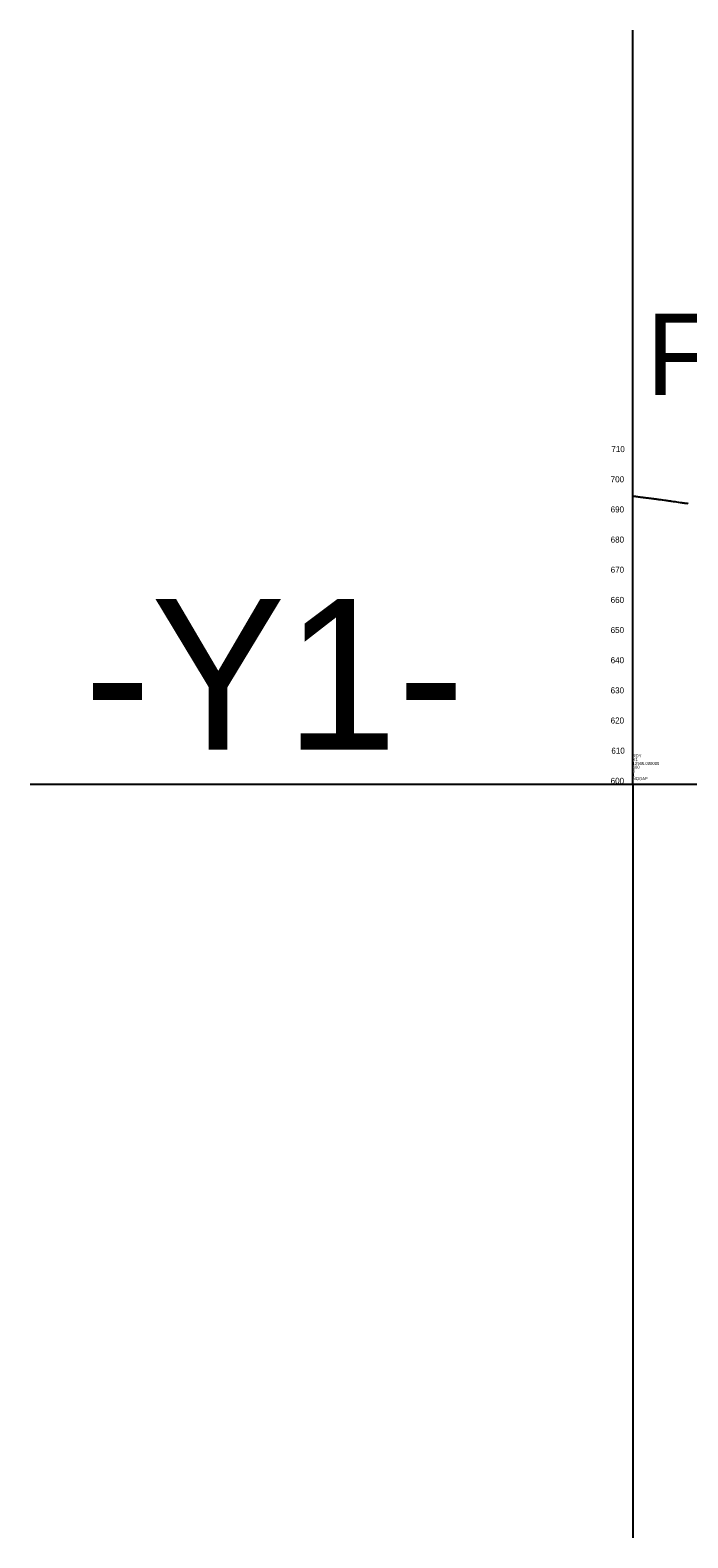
# Model space of a CAD drawing. Extents: x 1518255 to 1527303, y 471773 to 504546.
# Drawn here: x 1518570 to 1519662, y 496395 to 498895 of the extents above; entities that cross this region are included whole.
import ezdxf

# ---------------------------------------------------------------- set-up
doc = ezdxf.new("R2010")
doc.units = 0
for name, color, linetype in [('Default', 7, 'Continuous'), ('Exist Profile Cell', 7, 'Continuous'), ('Exist Vertical Profile Ground Line', 7, 'Continuous'), ('Exist Vertical Profile Vertical Axis Label', 7, 'Continuous')]:
    doc.layers.add(name, color=color, linetype=linetype)

msp = doc.modelspace()

# ---------------------------------------------------------------- linework, layer by layer
at = {"layer": 'Default'}
msp.add_line((1518570.4, 497645), (1519570.4, 497645), dxfattribs=at)
at = {"layer": 'Exist Profile Cell'}
for q in [(1519570.4, 498895), (1521670.4, 497645), (1519570.4, 496395)]:
    msp.add_line((1519570.4, 497645), q, dxfattribs=at)
at = {"layer": 'Exist Vertical Profile Ground Line'}
msp.add_lwpolyline([(1519570.4, 498122.7), (1519570.7, 498122.6), (1519571.2, 498122.6), (1519572.6, 498122.4), (1519574.1, 498122.3), (1519574.4, 498122.2), (1519575, 498122.2), (1519576.2, 498122), (1519577, 498121.9), (1519578.3, 498121.7), (1519580, 498121.4), (1519582.7, 498121.1), (1519583.6, 498120.9), (1519585.1, 498120.8), (1519585.6, 498120.7), (1519586.2, 498120.6), (1519587.3, 498120.5), (1519588.4, 498120.3), (1519590.2, 498120.1), (1519590.9, 498120), (1519591.3, 498120), (1519592.8, 498119.8), (1519594.2, 498119.6), (1519595.3, 498119.5), (1519596.4, 498119.3), (1519597.1, 498119.2), (1519598.3, 498119.1), (1519600, 498118.9), (1519600.3, 498118.8), (1519601.9, 498118.6), (1519602.8, 498118.5), (1519603.8, 498118.4), (1519605.4, 498118.2), (1519605.7, 498118.1), (1519607.4, 498117.9), (1519608.6, 498117.7), (1519609.3, 498117.6), (1519610.4, 498117.5), (1519611.5, 498117.3), (1519612.9, 498117.1), (1519614, 498116.9), (1519614.4, 498116.9), (1519614.8, 498116.8), (1519615.5, 498116.7), (1519617.2, 498116.5), (1519619.5, 498116.2), (1519620.5, 498116.1), (1519623, 498115.8), (1519625.9, 498115.4), (1519626.3, 498115.3), (1519628.7, 498115), (1519630.6, 498114.7), (1519631.9, 498114.5), (1519633, 498114.3), (1519634.5, 498114.1), (1519635.6, 498113.9), (1519637.4, 498113.7), (1519639.7, 498113.3), (1519640.8, 498113.2), (1519643.1, 498112.8), (1519646, 498112.4), (1519646.5, 498112.3), (1519648.9, 498111.9), (1519649.8, 498111.8), (1519650.7, 498111.7), (1519651.4, 498111.6), (1519651.8, 498111.6), (1519653.1, 498111.4), (1519654.7, 498111.1), (1519655.8, 498111), (1519656.9, 498110.9), (1519657.5, 498110.8), (1519658.7, 498110.7), (1519659.9, 498110.6), (1519660.4, 498110.5), (1519660.8, 498110.5), (1519662.4, 498110.2)], dxfattribs=at)

# ---------------------------------------------------------------- texts
at = {"layer": 'Default'}
for s, height, p in [('FOR INFORMATION ONLY', 135, (1519593.4, 498289.9)), ('-Y1-', 250, (1518659.7, 497701.8))]:
    msp.add_text(s, height=height, dxfattribs=at).set_placement(p)
at = {"layer": 'Exist Profile Cell'}
for s, p in [('Y1', (1519570.4, 497683)), ('600', (1519570.4, 497670.4)), ('12500.000000', (1519570.4, 497676.7)), ('RDY', (1519570.4, 497689.4)), ('5', (1519570.4, 497664)), ('1', (1519570.4, 497657.7)), ('NOGAP', (1519570.4, 497651.4))]:
    msp.add_text(s, height=5, dxfattribs=at).set_placement(p)
at = {"layer": 'Exist Vertical Profile Vertical Axis Label'}
for s, p in [('710', (1519535, 498195.3)), ('700', (1519533.8, 498145.3)), ('690', (1519533.8, 498095.3)), ('680', (1519533.8, 498045.3)), ('670', (1519533.8, 497995.3)), ('660', (1519533.8, 497945.3)), ('650', (1519533.8, 497895.3)), ('640', (1519533.8, 497845.3)), ('630', (1519533.8, 497795.3)), ('620', (1519533.8, 497745.3)), ('610', (1519535, 497695.3)), ('600', (1519533.8, 497645.3))]:
    msp.add_text(s, height=10, dxfattribs=at).set_placement(p)

doc.saveas('drawing.dxf')
